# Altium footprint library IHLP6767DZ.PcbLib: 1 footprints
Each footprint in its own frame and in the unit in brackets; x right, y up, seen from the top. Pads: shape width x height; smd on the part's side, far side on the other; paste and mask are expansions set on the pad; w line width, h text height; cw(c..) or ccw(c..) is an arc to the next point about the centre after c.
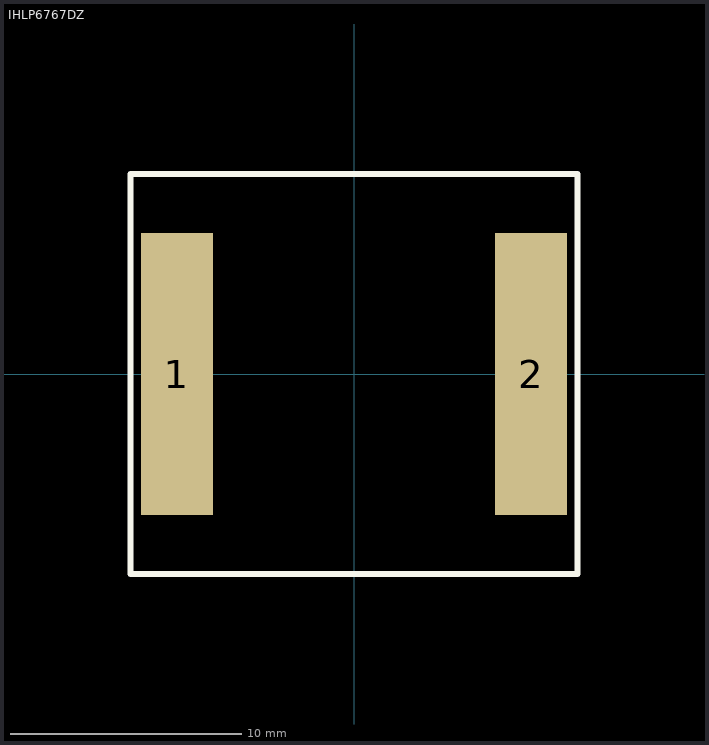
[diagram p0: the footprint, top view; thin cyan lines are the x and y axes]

## IHLP6767DZ [mm] "IHLP6767DZ VISHAY DALE INDUCTOR"
height 4
pads (2):
  rect 3.125x12.19 smd: 1(-7.648,0) 2(7.648,0)
Top Overlay:
  lines w0.254: -9.652,-8.636 -9.652,8.636 9.652,8.636 9.652,-8.636 -9.652,-8.636
M5 Assembly Top:
  text ".Designator" at 0,0 h1.02
3D body: height 4, standoff 0, extent -9.652,-8.636 9.652,8.636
